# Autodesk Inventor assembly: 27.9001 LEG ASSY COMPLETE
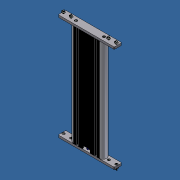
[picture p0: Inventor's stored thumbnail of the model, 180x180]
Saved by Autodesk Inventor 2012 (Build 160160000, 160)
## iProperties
Created: 2013-12
Part Number: 27.9001 LEG ASSY COMPLETE
Document SubType Name: Assembly
Designer: Admin
Author: Admin
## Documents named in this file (9)
- C:\Andys Backup Data\ANDY'S INVENTOR\INVENTOR LIBRARIES\PARTS LIBRARY\HYDRAULIC VERTICAL ADJUSTMENT\27.9001Telescoping Twin Leg System\27.9001 LEG ASSY COMPLETE.iam
- C:\Andys Backup Data\ANDY'S INVENTOR\INVENTOR LIBRARIES\PARTS LIBRARY\HYDRAULIC VERTICAL ADJUSTMENT\27.9001Telescoping Twin Leg System\SUBCOMPONENTS\27.9001 OUTER LEG PROFILE.ipt
- C:\Andys Backup Data\ANDY'S INVENTOR\INVENTOR LIBRARIES\PARTS LIBRARY\HYDRAULIC VERTICAL ADJUSTMENT\27.9001Telescoping Twin Leg System\SUBCOMPONENTS\27.9001 INNER LEG PROFILE.ipt
- C:\Andys Backup Data\ANDY'S INVENTOR\INVENTOR LIBRARIES\PARTS LIBRARY\HYDRAULIC VERTICAL ADJUSTMENT\27.9001Telescoping Twin Leg System\SUBCOMPONENTS\CEx30 cylinder\CEx30.iam
- C:\Andys Backup Data\ANDY'S INVENTOR\INVENTOR LIBRARIES\PARTS LIBRARY\HYDRAULIC VERTICAL ADJUSTMENT\27.9001Telescoping Twin Leg System\SUBCOMPONENTS\27.9001_2 TOP MOUNTING PLATE.ipt
- C:\Andys Backup Data\ANDY'S INVENTOR\INVENTOR LIBRARIES\PARTS LIBRARY\FASTENING ELEMENTS\SCREWS CAP\21.1206 M8X30.ipt
- C:\Andys Backup Data\ANDY'S INVENTOR\INVENTOR LIBRARIES\PARTS LIBRARY\FASTENING ELEMENTS\SCREWS CAP\21.1202 M8X20.ipt
- C:\Andys Backup Data\ANDY'S INVENTOR\INVENTOR LIBRARIES\PARTS LIBRARY\FASTENING ELEMENTS\NUTS\21.1351_2 M8 SQUARE NUT POS FXG.ipt
- C:\Andys Backup Data\ANDY'S INVENTOR\INVENTOR LIBRARIES\PARTS LIBRARY\HYDRAULIC VERTICAL ADJUSTMENT\27.9001Telescoping Twin Leg System\SUBCOMPONENTS\27.9001_3 BOTTOM MOUNTING PLATE.ipt
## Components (25 placed, 8 different names)
1. 27.9001 OUTER LEG PROFILE:1 — Flush:1, Flush:2, Flush:3, Insert:1, Mate:1, Flush:4, Angle:1
2. 27.9001 INNER LEG PROFILE:1 — Flush:1, Flush:2, Flush:3, Insert:12, Mate:3
3. CEx30:1 [sub-assembly] — Flush:4, Mate:2, Angle:1
4. 27.9001_2 TOP MOUNTING PLATE:1 — Insert:1, Mate:1, Mate:2, Insert:2, Insert:3, Insert:4, Insert:5, Insert:6, Insert:7, Insert:8, Insert:9, Insert:10, Insert:11, Angle:2, Angle:3, Angle:4, Angle:5
5. 21.1206 M8 x 30:1 — Insert:2
6. 21.1206 M8 x 30:2 — Insert:3
7. 21.1202  M8 x 20:1 — Insert:4
8. 21.1202  M8 x 20:2 — Insert:5
9. 21.1202  M8 x 20:3 — Insert:7
10. 21.1202  M8 x 20:4 — Insert:6
11. 21.1351_2 M8 SQUARE NUT POS FXG:1 — Insert:8, Angle:2
12. 21.1351_2 M8 SQUARE NUT POS FXG:2 — Insert:9, Angle:3
13. 21.1351_2 M8 SQUARE NUT POS FXG:3 — Insert:10, Angle:4
14. 21.1351_2 M8 SQUARE NUT POS FXG:4 — Insert:11, Angle:5
15. 27.9001_3 BOTTOM MOUNTING PLATE:1 — Insert:12, Mate:3, Insert:13, Insert:14, Insert:15, Insert:16, Insert:17, Insert:18, Insert:19, Insert:20, Insert:21, Insert:22
16. 21.1206 M8 x 30:3 — Insert:13
17. 21.1206 M8 x 30:4 — Insert:14
18. 21.1202  M8 x 20:5 — Insert:15
19. 21.1202  M8 x 20:6 — Insert:16
20. 21.1202  M8 x 20:7 — Insert:17
21. 21.1202  M8 x 20:8 — Insert:18
22. 21.1351_2 M8 SQUARE NUT POS FXG:5 — Insert:22
23. 21.1351_2 M8 SQUARE NUT POS FXG:6 — Insert:20
24. 21.1351_2 M8 SQUARE NUT POS FXG:7 — Insert:19
25. 21.1351_2 M8 SQUARE NUT POS FXG:8 — Insert:21
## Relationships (34: Insert 22, Angle 5, Flush 4, Mate 3)
- Flush:1: 27.9001 OUTER LEG PROFILE:1 ↔ 27.9001 INNER LEG PROFILE:1
- Flush:2: 27.9001 OUTER LEG PROFILE:1 ↔ 27.9001 INNER LEG PROFILE:1
- Flush:3: 27.9001 OUTER LEG PROFILE:1 ↔ 27.9001 INNER LEG PROFILE:1
- Insert:1: 27.9001 OUTER LEG PROFILE:1 ↔ 27.9001_2 TOP MOUNTING PLATE:1
- Mate:1: 27.9001 OUTER LEG PROFILE:1 ↔ 27.9001_2 TOP MOUNTING PLATE:1
- Flush:4: 27.9001 OUTER LEG PROFILE:1 ↔ CEx30:1
- Mate:2: CEx30:1 ↔ 27.9001_2 TOP MOUNTING PLATE:1
- Angle:1: 27.9001 OUTER LEG PROFILE:1 ↔ CEx30:1
- Insert:2: 27.9001_2 TOP MOUNTING PLATE:1 ↔ 21.1206 M8 x 30:1
- Insert:3: 27.9001_2 TOP MOUNTING PLATE:1 ↔ 21.1206 M8 x 30:2
- Insert:4: 27.9001_2 TOP MOUNTING PLATE:1 ↔ 21.1202  M8 x 20:1
- Insert:5: 27.9001_2 TOP MOUNTING PLATE:1 ↔ 21.1202  M8 x 20:2
- Insert:6: 27.9001_2 TOP MOUNTING PLATE:1 ↔ 21.1202  M8 x 20:4
- Insert:7: 27.9001_2 TOP MOUNTING PLATE:1 ↔ 21.1202  M8 x 20:3
- Insert:8: 27.9001_2 TOP MOUNTING PLATE:1 ↔ 21.1351_2 M8 SQUARE NUT POS FXG:1
- Insert:9: 27.9001_2 TOP MOUNTING PLATE:1 ↔ 21.1351_2 M8 SQUARE NUT POS FXG:2
- Insert:10: 27.9001_2 TOP MOUNTING PLATE:1 ↔ 21.1351_2 M8 SQUARE NUT POS FXG:3
- Insert:11: 27.9001_2 TOP MOUNTING PLATE:1 ↔ 21.1351_2 M8 SQUARE NUT POS FXG:4
- Angle:2: 27.9001_2 TOP MOUNTING PLATE:1 ↔ 21.1351_2 M8 SQUARE NUT POS FXG:1
- Angle:3: 27.9001_2 TOP MOUNTING PLATE:1 ↔ 21.1351_2 M8 SQUARE NUT POS FXG:2
- Angle:4: 27.9001_2 TOP MOUNTING PLATE:1 ↔ 21.1351_2 M8 SQUARE NUT POS FXG:3
- Angle:5: 27.9001_2 TOP MOUNTING PLATE:1 ↔ 21.1351_2 M8 SQUARE NUT POS FXG:4
- Insert:12: 27.9001 INNER LEG PROFILE:1 ↔ 27.9001_3 BOTTOM MOUNTING PLATE:1
- Mate:3: 27.9001 INNER LEG PROFILE:1 ↔ 27.9001_3 BOTTOM MOUNTING PLATE:1
- Insert:13: 27.9001_3 BOTTOM MOUNTING PLATE:1 ↔ 21.1206 M8 x 30:3
- Insert:14: 27.9001_3 BOTTOM MOUNTING PLATE:1 ↔ 21.1206 M8 x 30:4
- Insert:15: 27.9001_3 BOTTOM MOUNTING PLATE:1 ↔ 21.1202  M8 x 20:5
- Insert:16: 27.9001_3 BOTTOM MOUNTING PLATE:1 ↔ 21.1202  M8 x 20:6
- Insert:17: 27.9001_3 BOTTOM MOUNTING PLATE:1 ↔ 21.1202  M8 x 20:7
- Insert:18: 27.9001_3 BOTTOM MOUNTING PLATE:1 ↔ 21.1202  M8 x 20:8
- Insert:19: 27.9001_3 BOTTOM MOUNTING PLATE:1 ↔ 21.1351_2 M8 SQUARE NUT POS FXG:7
- Insert:20: 27.9001_3 BOTTOM MOUNTING PLATE:1 ↔ 21.1351_2 M8 SQUARE NUT POS FXG:6
- Insert:21: 27.9001_3 BOTTOM MOUNTING PLATE:1 ↔ 21.1351_2 M8 SQUARE NUT POS FXG:8
- Insert:22: 27.9001_3 BOTTOM MOUNTING PLATE:1 ↔ 21.1351_2 M8 SQUARE NUT POS FXG:5
